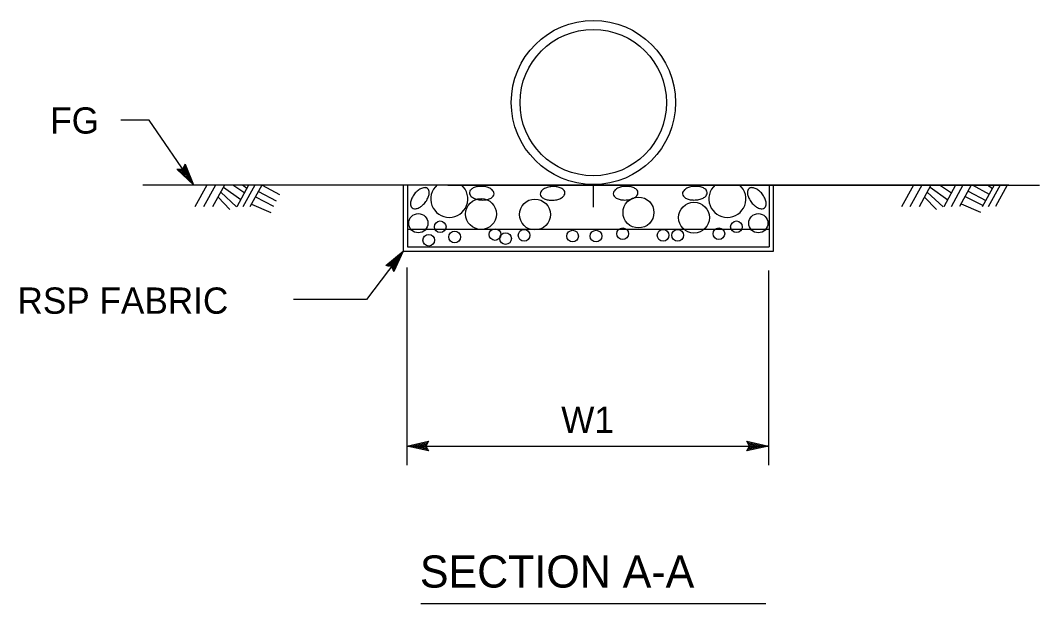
# Model space of a CAD drawing. Extents: x 6707692 to 6708868, y 1870875 to 1871658.
# Drawn here: x 6708138.6 to 6708367.4, y 1871310.4 to 1871441.4 of the extents above; entities that cross this region are included whole.
import ezdxf

# ---------------------------------------------------------------- set-up
doc = ezdxf.new("R2010")
doc.units = 0
doc.layers.add('Level 60', color=7, linetype='Continuous')

msp = doc.modelspace()

# ---------------------------------------------------------------- linework, layer by layer
at = {"layer": 'Level 60'}
for p, q in [((6708167.49, 1871419.01), (6708161.12, 1871419.01)), ((6708177.41, 1871404.43), (6708167.49, 1871419.01)), ((6708175.01, 1871407.94), (6708173.73, 1871407.87)), ((6708175.01, 1871407.94), (6708173.73, 1871407.87)), ((6708173.73, 1871407.87), (6708173.73, 1871407.87)), ((6708173.73, 1871407.87), (6708173.73, 1871407.87)), ((6708173.74, 1871407.88), (6708175.01, 1871407.95)), ((6708177.41, 1871404.43), (6708173.74, 1871407.88)), ((6708173.74, 1871407.88), (6708173.74, 1871407.88)), ((6708176.76, 1871405.37), (6708174.09, 1871407.89)), ((6708176.14, 1871406.3), (6708174.41, 1871407.93)), ((6708175.5, 1871407.24), (6708174.76, 1871407.93)), ((6708175.01, 1871407.95), (6708175.55, 1871409.11)), ((6708175.54, 1871409.09), (6708175.01, 1871407.94)), ((6708175.54, 1871409.09), (6708175.01, 1871407.94)), ((6708175.12, 1871408.2), (6708175.5, 1871407.24)), ((6708175.27, 1871408.48), (6708176.14, 1871406.3)), ((6708175.41, 1871408.8), (6708176.77, 1871405.36)), ((6708175.54, 1871409.09), (6708175.54, 1871409.09)), ((6708175.54, 1871409.09), (6708175.54, 1871409.09)), ((6708175.55, 1871409.11), (6708175.55, 1871409.11)), ((6708175.55, 1871409.11), (6708177.41, 1871404.43)), ((6708177.41, 1871404.43), (6708176.4, 1871405.91)), ((6708166.08, 1871404.43), (6708234.56, 1871404.43)), ((6708177.41, 1871404.43), (6708360.54, 1871404.43)), ((6708177.41, 1871404.43), (6708177.41, 1871404.43)), ((6708177.41, 1871404.43), (6708177.41, 1871404.43)), ((6708177.41, 1871404.43), (6708177.41, 1871404.43)), ((6708177.82, 1871399.56), (6708180.5, 1871404.43)), ((6708179.75, 1871399.56), (6708182.43, 1871404.43)), ((6708181.8, 1871399.62), (6708184.44, 1871404.43)), ((6708183.56, 1871402.82), (6708187.1, 1871399.54)), ((6708184.16, 1871403.92), (6708188.09, 1871401.15)), ((6708186.28, 1871404.43), (6708188.93, 1871402.7)), ((6708187.24, 1871399.63), (6708189.88, 1871404.43)), ((6708188.47, 1871404.43), (6708189.44, 1871403.7)), ((6708188.6, 1871399.63), (6708191.25, 1871404.43)), ((6708190.18, 1871399.6), (6708192.84, 1871404.43)), ((6708192.04, 1871402.98), (6708195.98, 1871400.88)), ((6708192.82, 1871404.39), (6708196.72, 1871402.31)), ((6708224.51, 1871404.43), (6708224.51, 1871389.56)), ((6708225.5, 1871404.43), (6708225.5, 1871390.56)), ((6708234.56, 1871404.37), (6708367.44, 1871404.37)), ((6708267.2, 1871404.43), (6708267.2, 1871399.41)), ((6708290.19, 1871404.43), (6708315.85, 1871404.43)), ((6708306.71, 1871404.43), (6708306.71, 1871390.54)), ((6708307.7, 1871389.56), (6708307.7, 1871404.43)), ((6708317.19, 1871404.43), (6708332.36, 1871404.43)), ((6708336.49, 1871399.57), (6708339.16, 1871404.43)), ((6708338.41, 1871399.57), (6708341.09, 1871404.43)), ((6708340.46, 1871399.63), (6708343.1, 1871404.43)), ((6708342.22, 1871402.83), (6708345.76, 1871399.55)), ((6708342.83, 1871403.93), (6708346.81, 1871401.12)), ((6708344.95, 1871404.43), (6708347.66, 1871402.67)), ((6708345.98, 1871399.63), (6708348.63, 1871404.43)), ((6708347.66, 1871399.63), (6708350.3, 1871404.43)), ((6708349.52, 1871399.69), (6708352.13, 1871404.43)), ((6708351.38, 1871403.07), (6708355.37, 1871400.95)), ((6708352.27, 1871404.43), (6708356.15, 1871402.36)), ((6708354.61, 1871399.57), (6708357.29, 1871404.43)), ((6708355.76, 1871404.43), (6708356.84, 1871403.62)), ((6708355.98, 1871399.57), (6708358.66, 1871404.43)), ((6708357.59, 1871399.69), (6708360.2, 1871404.43)), ((6708182.94, 1871401.71), (6708185.61, 1871398.92)), ((6708191.37, 1871401.76), (6708195.42, 1871399.7)), ((6708341.61, 1871401.72), (6708344.27, 1871398.92)), ((6708350.71, 1871401.85), (6708354.74, 1871399.8)), ((6708190.47, 1871400.13), (6708194.8, 1871398.21)), ((6708349.81, 1871400.22), (6708354.14, 1871398.3)), ((6708225.5, 1871394.49), (6708306.71, 1871394.49)), ((6708224.51, 1871389.56), (6708216.27, 1871378.71)), ((6708224.51, 1871389.56), (6708224.51, 1871389.56)), ((6708224.51, 1871389.56), (6708307.7, 1871389.56)), ((6708225.5, 1871390.56), (6708306.71, 1871390.56)), ((6708220.66, 1871386.31), (6708220.66, 1871386.31)), ((6708222.41, 1871384.99), (6708222.41, 1871384.99)), ((6708225.33, 1871385.87), (6708225.33, 1871341.46)), ((6708306.59, 1871385.22), (6708306.59, 1871341.46)), ((6708216.27, 1871378.71), (6708199.88, 1871378.71)), ((6708225.33, 1871345.77), (6708230.24, 1871346.86)), ((6708225.33, 1871345.77), (6708306.59, 1871345.77)), ((6708225.33, 1871345.77), (6708227.12, 1871345.77)), ((6708230.24, 1871344.67), (6708225.33, 1871345.77)), ((6708225.33, 1871345.77), (6708225.33, 1871345.77)), ((6708230.06, 1871344.97), (6708226.46, 1871345.77)), ((6708226.47, 1871345.78), (6708230.05, 1871346.57)), ((6708227.59, 1871345.77), (6708229.9, 1871346.28)), ((6708229.87, 1871345.26), (6708227.59, 1871345.77)), ((6708228.72, 1871345.77), (6708229.71, 1871345.99)), ((6708229.73, 1871345.55), (6708228.72, 1871345.77)), ((6708230.24, 1871346.86), (6708229.59, 1871345.77)), ((6708229.59, 1871345.77), (6708230.24, 1871344.67)), ((6708230.24, 1871346.86), (6708230.24, 1871346.86)), ((6708302.33, 1871345.77), (6708301.68, 1871346.87)), ((6708301.68, 1871346.87), (6708301.68, 1871346.87)), ((6708301.68, 1871346.87), (6708306.59, 1871345.77)), ((6708306.59, 1871345.77), (6708301.68, 1871344.68)), ((6708301.68, 1871344.68), (6708302.33, 1871345.77)), ((6708301.85, 1871346.58), (6708305.46, 1871345.77)), ((6708305.45, 1871345.77), (6708301.87, 1871344.98)), ((6708304.33, 1871345.77), (6708302.01, 1871345.26)), ((6708302.04, 1871346.28), (6708304.33, 1871345.77)), ((6708302.19, 1871346), (6708303.2, 1871345.78)), ((6708303.2, 1871345.78), (6708302.21, 1871345.56)), ((6708306.59, 1871345.77), (6708304.79, 1871345.77)), ((6708306.59, 1871345.77), (6708306.59, 1871345.77)), ((6708230.24, 1871344.67), (6708230.24, 1871344.67)), ((6708301.68, 1871344.68), (6708301.68, 1871344.68)), ((6708228.47, 1871310.37), (6708305.95, 1871310.37))]:
    msp.add_line(p, q, dxfattribs=at)
msp.add_lwpolyline([(6708220.66, 1871386.31), (6708224.51, 1871389.56), (6708222.41, 1871384.98), (6708222.28, 1871385.3), (6708223.83, 1871388.65), (6708221, 1871386.27), (6708221.34, 1871386.23), (6708223.14, 1871387.76), (6708222.16, 1871385.61), (6708222.03, 1871385.93), (6708222.46, 1871386.86), (6708221.67, 1871386.2), (6708221.94, 1871386.17), (6708222.41, 1871384.98), (6708221.94, 1871386.17)], close=True, dxfattribs=at)
for centre, radius in [((6708267.24, 1871422.97), 18.44), ((6708267.2, 1871422.93), 16.44), ((6708242.01, 1871397.9), 3.47), ((6708254.11, 1871397.79), 3.47), ((6708277.36, 1871398.24), 3.47), ((6708289.83, 1871397.09), 3.47), ((6708227.92, 1871395.84), 2.16), ((6708304.28, 1871395.84), 2.16), ((6708232.83, 1871395.03), 1.31), ((6708299.37, 1871395.03), 1.31), ((6708236.08, 1871392.75), 1.31), ((6708245.15, 1871393.3), 1.31), ((6708247.51, 1871392.39), 1.31), ((6708251.68, 1871393.12), 1.31), ((6708262.57, 1871392.94), 1.31), ((6708267.83, 1871392.94), 1.31), ((6708273.82, 1871393.48), 1.31), ((6708282.89, 1871393.12), 1.31), ((6708286.16, 1871393.12), 1.31), ((6708295.41, 1871393.48), 1.31), ((6708230.27, 1871392.03), 1.31)]:
    msp.add_circle(centre, radius, dxfattribs=at)
for centre, radius, start, end in [((6708230.99, 1871399.3), 5.01, 128.6643, 141.5564), ((6708229.89, 1871400.67), 3.25, 112.6322, 128.6643), ((6708229.42, 1871401.82), 2.01, 88.4116, 112.6322), ((6708229.45, 1871402.94), 0.886, 51.5564, 88.4116), ((6708229.45, 1871402.94), 0.886, 14.7013, 51.5564), ((6708228.36, 1871402.66), 2.01, 350.4807, 14.7013), ((6708234.88, 1871401.31), 4.16, 131.4827, 48.5173), ((6708240.28, 1871402.69), 0.886, 140.0409, 176.8961), ((6708240.28, 1871402.69), 0.886, 176.8961, 213.7512), ((6708241.15, 1871401.96), 2.01, 115.8203, 140.0409), ((6708241.69, 1871400.85), 3.25, 99.7882, 115.8203), ((6708241.99, 1871399.11), 5.01, 86.8961, 99.7882), ((6708241.99, 1871399.11), 5.01, 74.0039, 86.8961), ((6708242.47, 1871400.81), 3.25, 57.9718, 74.0039), ((6708243.13, 1871401.86), 2.01, 33.7512, 57.9718), ((6708244.06, 1871402.48), 0.886, 356.8961, 33.7512), ((6708256.19, 1871402.42), 0.886, 146.2488, 183.1039), ((6708257.13, 1871401.8), 2.01, 122.0282, 146.2488), ((6708257.79, 1871400.75), 3.25, 105.9961, 122.0282), ((6708258.27, 1871399.05), 5.01, 93.1039, 105.9961), ((6708258.27, 1871399.05), 5.01, 80.2118, 93.1039), ((6708258.57, 1871400.79), 3.25, 64.1797, 80.2118), ((6708259.11, 1871401.91), 2.01, 39.9591, 64.1797), ((6708259.97, 1871402.63), 0.886, 3.1039, 39.9591), ((6708259.97, 1871402.63), 0.886, 326.2488, 3.1039), ((6708272.59, 1871402.48), 0.886, 146.2488, 183.1039), ((6708273.53, 1871401.86), 2.01, 122.0282, 146.2488), ((6708274.18, 1871400.81), 3.25, 105.9961, 122.0282), ((6708274.67, 1871399.11), 5.01, 93.1039, 105.9961), ((6708274.67, 1871399.11), 5.01, 80.2118, 93.1039), ((6708274.97, 1871400.85), 3.25, 64.1797, 80.2118), ((6708275.51, 1871401.96), 2.01, 39.9591, 64.1797), ((6708276.37, 1871402.69), 0.886, 3.1039, 39.9591), ((6708276.37, 1871402.69), 0.886, 326.2488, 3.1039), ((6708288.14, 1871402.48), 0.886, 146.2488, 183.1039), ((6708289.08, 1871401.86), 2.01, 122.0282, 146.2488), ((6708289.73, 1871400.81), 3.25, 105.9961, 122.0282), ((6708290.22, 1871399.11), 5.01, 93.1039, 105.9961), ((6708290.22, 1871399.11), 5.01, 80.2118, 93.1039), ((6708290.52, 1871400.85), 3.25, 64.1797, 80.2118), ((6708291.06, 1871401.96), 2.01, 39.9591, 64.1797), ((6708291.92, 1871402.69), 0.886, 3.1039, 39.9591), ((6708291.92, 1871402.69), 0.886, 326.2488, 3.1039), ((6708297.33, 1871401.31), 4.16, 131.4827, 48.5173), ((6708303.85, 1871402.66), 2.01, 165.2987, 189.5193), ((6708302.76, 1871402.94), 0.886, 128.4436, 165.2987), ((6708302.76, 1871402.94), 0.886, 91.5884, 128.4436), ((6708302.79, 1871401.82), 2.01, 67.3678, 91.5884), ((6708302.31, 1871400.67), 3.25, 51.3357, 67.3678), ((6708301.21, 1871399.3), 5.01, 38.4436, 51.3357), ((6708228.18, 1871400.26), 2.01, 170.4807, 194.7013), ((6708229.4, 1871400.06), 3.25, 154.4486, 170.4807), ((6708230.99, 1871399.3), 5.01, 141.5564, 154.4486), ((6708225.55, 1871403.62), 5.01, 308.6643, 321.5564), ((6708225.55, 1871403.62), 5.01, 321.5564, 334.4486), ((6708227.14, 1871402.86), 3.25, 334.4486, 350.4807), ((6708241.22, 1871403.31), 2.01, 213.7512, 237.9718), ((6708241.88, 1871404.36), 3.25, 237.9718, 254.0039), ((6708242.36, 1871406.06), 5.01, 254.0039, 266.8961), ((6708242.36, 1871406.06), 5.01, 266.8961, 279.7882), ((6708242.66, 1871404.32), 3.25, 279.7882, 295.8203), ((6708243.2, 1871403.21), 2.01, 295.8203, 320.0409), ((6708244.06, 1871402.48), 0.886, 320.0409, 356.8961), ((6708256.19, 1871402.42), 0.886, 183.1039, 219.9591), ((6708257.06, 1871403.15), 2.01, 219.9591, 244.1797), ((6708257.6, 1871404.26), 3.25, 244.1797, 260.2118), ((6708257.9, 1871406), 5.01, 260.2118, 273.1039), ((6708257.9, 1871406), 5.01, 273.1039, 285.9961), ((6708258.38, 1871404.3), 3.25, 285.9961, 302.0282), ((6708259.04, 1871403.25), 2.01, 302.0282, 326.2488), ((6708272.59, 1871402.48), 0.886, 183.1039, 219.9591), ((6708273.45, 1871403.21), 2.01, 219.9591, 244.1797), ((6708273.99, 1871404.32), 3.25, 244.1797, 260.2118), ((6708274.29, 1871406.06), 5.01, 260.2118, 273.1039), ((6708274.29, 1871406.06), 5.01, 273.1039, 285.9961), ((6708274.78, 1871404.36), 3.25, 285.9961, 302.0282), ((6708275.43, 1871403.31), 2.01, 302.0282, 326.2488), ((6708288.14, 1871402.48), 0.886, 183.1039, 219.9591), ((6708289.01, 1871403.21), 2.01, 219.9591, 244.1797), ((6708289.54, 1871404.32), 3.25, 244.1797, 260.2118), ((6708289.84, 1871406.06), 5.01, 260.2118, 273.1039), ((6708289.84, 1871406.06), 5.01, 273.1039, 285.9961), ((6708290.33, 1871404.36), 3.25, 285.9961, 302.0282), ((6708290.99, 1871403.31), 2.01, 302.0282, 326.2488), ((6708305.07, 1871402.86), 3.25, 189.5193, 205.5514), ((6708306.66, 1871403.62), 5.01, 205.5514, 218.4436), ((6708306.66, 1871403.62), 5.01, 218.4436, 231.3357), ((6708301.21, 1871399.3), 5.01, 25.5514, 38.4436), ((6708302.8, 1871400.06), 3.25, 9.5193, 25.5514), ((6708304.02, 1871400.26), 2.01, 345.2987, 9.5193), ((6708227.09, 1871399.98), 0.886, 194.7013, 231.5564), ((6708227.09, 1871399.98), 0.886, 231.5564, 268.4116), ((6708227.12, 1871401.1), 2.01, 268.4116, 292.6322), ((6708226.65, 1871402.24), 3.25, 292.6322, 308.6643), ((6708305.56, 1871402.24), 3.25, 231.3357, 247.3678), ((6708305.08, 1871401.1), 2.01, 247.3678, 271.5884), ((6708305.11, 1871399.98), 0.886, 271.5884, 308.4436), ((6708305.11, 1871399.98), 0.886, 308.4436, 345.2987)]:
    msp.add_arc(centre, radius, start, end, dxfattribs=at)

# ---------------------------------------------------------------- texts
for s, height, p in [('FG', 5.9, (6708145.26, 1871415.97)), ('RSP FABRIC', 5.9, (6708137.91, 1871375.5)), ('W1', 5.9, (6708260.01, 1871348.72)), ('SECTION A-A', 7.2111, (6708228.28, 1871313.98))]:
    msp.add_text(s, height=height, dxfattribs=at).set_placement(p)

doc.saveas('drawing.dxf')
